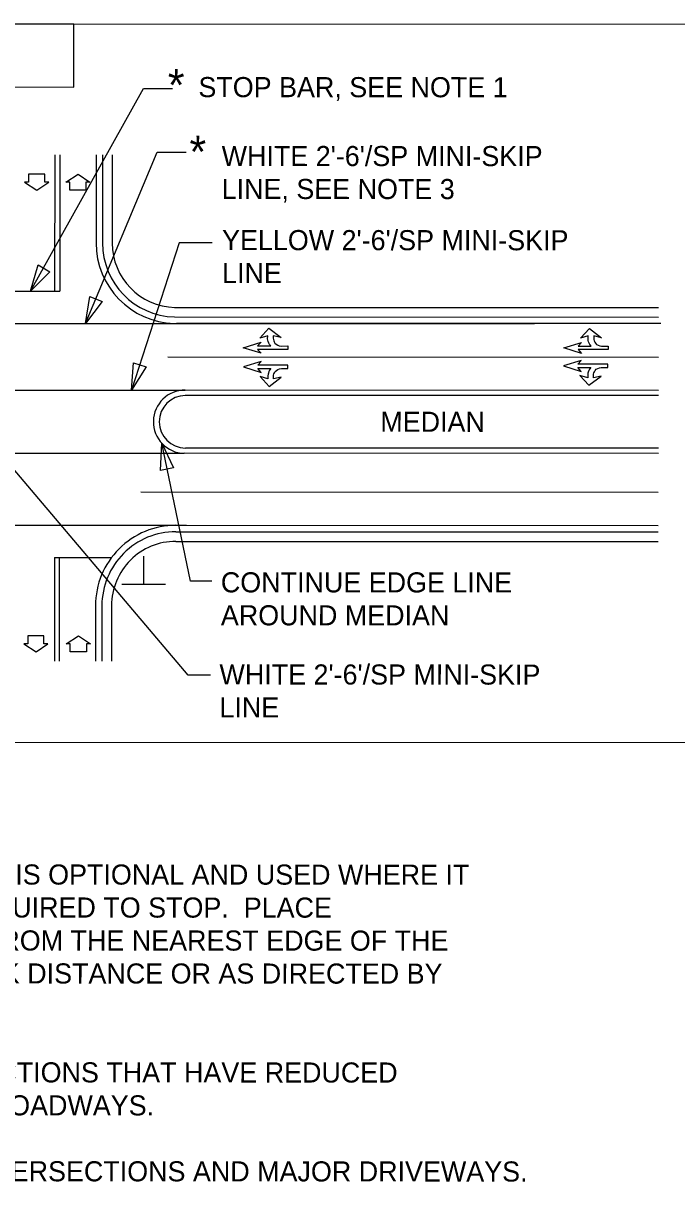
# Model space of a CAD drawing. Extents: x 50667 to 52386, y 46650 to 50479.
# Drawn here: x 51802.6 to 52036.3, y 47079.1 to 47493.3 of the extents above; entities that cross this region are included whole.
import ezdxf

# ---------------------------------------------------------------- set-up
doc = ezdxf.new("R2010")
doc.units = 0
for name, color, linetype in [('Default', 7, 'Continuous'), ('DEV TUBULAR MARKER SECTIONAL VIEW CELL', 7, 'Continuous'), ('Exist Guardrail Text', 7, 'Continuous'), ('Exist Hydro Spring Leader', 7, 'Continuous'), ('Exist Hydro Spring Text', 7, 'Continuous'), ('Exist Utilities Telephone Pole Text Tag Number', 7, 'Continuous'), ('Gray Area Fill Shapes', 7, 'Continuous'), ('Matchline', 7, 'Continuous'), ('Old_Level_49', 7, 'Continuous'), ('Prop EOT Dash', 7, 'Continuous')]:
    doc.layers.add(name, color=color, linetype=linetype)

msp = doc.modelspace()

# ---------------------------------------------------------------- linework, layer by layer
at = {"layer": 'Default'}
for p, q in [((52075.53, 47492.74), (50973.75, 47493.26)), ((51805.21, 47397.44), (51845.59, 47469.94)), ((51845.59, 47469.94), (51855.97, 47469.94)), ((51824.88, 47385.94), (51850.49, 47447.19)), ((51850.49, 47447.19), (51860.87, 47447.19)), ((51813.87, 47446.16), (51813.85, 47397.44)), ((51815.71, 47446.16), (51815.69, 47397.44)), ((51858.35, 47414.74), (51841.34, 47362.08)), ((51870.2, 47414.73), (51858.35, 47414.74)), ((51795.28, 47397.45), (51815.69, 47397.44)), ((51825.58, 47387.99), (51824.88, 47385.94)), ((52030.54, 47385.84), (51857.37, 47385.92)), ((52029.68, 47362), (51860.56, 47362.08)), ((52029.68, 47360.1), (51860.56, 47360.18)), ((51861.63, 47260.23), (51794.41, 47339.52)), ((51862.36, 47293.74), (51852.12, 47343.14)), ((52029.67, 47339.41), (51860.19, 47339.49)), ((52029.67, 47341.29), (51860.57, 47341.37)), ((51813.78, 47302.29), (51813.76, 47265.22)), ((51813.78, 47302.29), (51834.19, 47302.28)), ((51815.5, 47302.29), (51815.48, 47265.22)), ((51870.04, 47293.73), (51862.36, 47293.74)), ((51828.43, 47285.03), (51828.42, 47265.22)), ((51830.73, 47285.03), (51830.72, 47265.21)), ((51834.18, 47285.03), (51834.17, 47265.21)), ((51869.61, 47260.23), (51861.63, 47260.23)), ((52075.41, 47236.01), (50973.63, 47236.53))]:
    msp.add_line(p, q, dxfattribs=at)
for centre, radius, start, end in [((51857.4, 47414.66), 28.75, 179.9734, 268.494), ((51857.4, 47414.66), 26.45, 179.9734, 268.494), ((51857.4, 47414.66), 23, 179.9734, 268.494), ((51860.45, 47350.78), 11.3, 89.479, 268.6341), ((51860.64, 47350.77), 9.4, 90.4385, 269.5936), ((51857.19, 47285.01), 28.75, 89.9734, 179.9734), ((51857.19, 47285.01), 26.45, 89.9734, 179.9734), ((51857.19, 47285.01), 23, 89.9734, 179.9734)]:
    msp.add_arc(centre, radius, start, end, dxfattribs=at)
at = {"layer": 'DEV TUBULAR MARKER SECTIONAL VIEW CELL'}
msp.add_lwpolyline([(51462.35, 47470.51), (51820.66, 47470.34), (51820.67, 47492.86), (51462.36, 47493.03)], close=True, dxfattribs=at)
at = {"layer": 'Exist Guardrail Text'}
for p, q in [((51845.73, 47292.65), (51845.74, 47302.71)), ((51837.91, 47292.65), (51853.43, 47292.65))]:
    msp.add_line(p, q, dxfattribs=at)
at = {"layer": 'Exist Hydro Spring Leader'}
msp.add_line((51770.73, 47362.1), (51860.55, 47362.06), dxfattribs=at)
at = {"layer": 'Exist Hydro Spring Text'}
for p, q in [((51773.03, 47385.96), (51856.64, 47385.92)), ((51774.15, 47339.53), (51859.91, 47339.49)), ((51772.11, 47313.8), (51861.02, 47313.76))]:
    msp.add_line(p, q, dxfattribs=at)
at = {"layer": 'Exist Utilities Telephone Pole Text Tag Number'}
for p, q in [((51854.28, 47373.96), (52029.68, 47373.88)), ((51844.71, 47325.66), (52029.66, 47325.58))]:
    msp.add_line(p, q, dxfattribs=at)
at = {"layer": 'Gray Area Fill Shapes'}
for p, q in [((51828.65, 47446.15), (51828.64, 47413.95)), ((51830.95, 47446.15), (51830.94, 47413.95)), ((51834.4, 47446.15), (51834.39, 47413.95))]:
    msp.add_line(p, q, dxfattribs=at)
for points in [[(51804.54, 47439.32), (51804.54, 47436.44), (51803.1, 47436.44), (51807.46, 47433.57), (51811.72, 47436.44), (51810.29, 47436.44), (51810.29, 47439.32)], [(51819.28, 47433.53), (51819.28, 47436.4), (51817.85, 47436.4), (51822.21, 47439.28), (51826.47, 47436.4), (51825.03, 47436.4), (51825.03, 47433.52)], [(51804.27, 47274.29), (51804.27, 47271.41), (51802.83, 47271.41), (51807.19, 47268.54), (51811.45, 47271.41), (51810.02, 47271.41), (51810.02, 47274.29)], [(51819.44, 47268.5), (51819.44, 47271.37), (51818, 47271.37), (51822.37, 47274.25), (51826.63, 47271.37), (51825.19, 47271.37), (51825.19, 47268.49)]]:
    msp.add_lwpolyline(points, close=True, dxfattribs=at)
at = {"layer": 'Matchline'}
for points in [[(51897.18, 47376.6), (51886.38, 47376.61), (51887.63, 47375.26), (51881.3, 47377.23), (51887.63, 47379.2), (51886.38, 47377.85), (51891.08, 47377.85), (51890.63, 47378.42), (51890.37, 47378.86), (51890.17, 47379.42), (51890.07, 47379.88), (51889.99, 47380.46), (51890.02, 47381.48), (51887.22, 47380.66), (51890.44, 47384.18), (51894.8, 47380.86), (51891.99, 47381.48), (51892.01, 47380.68), (51892.03, 47380.2), (51892.15, 47379.72), (51892.37, 47379.3), (51892.61, 47378.88), (51893.04, 47378.46), (51893.58, 47378.14), (51894.16, 47377.94), (51894.82, 47377.84), (51897.18, 47377.85)], [(51897.18, 47376.6), (51886.38, 47376.61), (51887.63, 47375.26), (51881.3, 47377.23), (51887.63, 47379.2), (51886.38, 47377.85), (51891.08, 47377.85), (51890.63, 47378.42), (51890.37, 47378.86), (51890.17, 47379.42), (51890.07, 47379.88), (51889.99, 47380.46), (51890.02, 47381.48), (51887.22, 47380.66), (51890.44, 47384.18), (51894.8, 47380.86), (51891.99, 47381.48), (51892.01, 47380.68), (51892.03, 47380.2), (51892.15, 47379.72), (51892.37, 47379.3), (51892.61, 47378.88), (51893.04, 47378.46), (51893.58, 47378.14), (51894.16, 47377.94), (51894.82, 47377.84), (51897.18, 47377.85)], [(52011.75, 47376.55), (52000.95, 47376.55), (52002.2, 47375.2), (51995.87, 47377.18), (52002.2, 47379.15), (52000.96, 47377.8), (52005.65, 47377.8), (52005.2, 47378.37), (52004.94, 47378.81), (52004.74, 47379.37), (52004.64, 47379.82), (52004.56, 47380.4), (52004.59, 47381.43), (52001.79, 47380.6), (52005.01, 47384.13), (52009.37, 47380.81), (52006.56, 47381.43), (52006.58, 47380.62), (52006.6, 47380.14), (52006.72, 47379.66), (52006.94, 47379.25), (52007.18, 47378.83), (52007.61, 47378.41), (52008.15, 47378.09), (52008.73, 47377.89), (52009.39, 47377.79), (52011.75, 47377.79)], [(52011.75, 47376.55), (52000.95, 47376.55), (52002.2, 47375.2), (51995.87, 47377.18), (52002.2, 47379.15), (52000.96, 47377.8), (52005.65, 47377.8), (52005.2, 47378.37), (52004.94, 47378.81), (52004.74, 47379.37), (52004.64, 47379.82), (52004.56, 47380.4), (52004.59, 47381.43), (52001.79, 47380.6), (52005.01, 47384.13), (52009.37, 47380.81), (52006.56, 47381.43), (52006.58, 47380.62), (52006.6, 47380.14), (52006.72, 47379.66), (52006.94, 47379.25), (52007.18, 47378.83), (52007.61, 47378.41), (52008.15, 47378.09), (52008.73, 47377.89), (52009.39, 47377.79), (52011.75, 47377.79)], [(51897.25, 47371), (51886.45, 47371.01), (51887.7, 47372.36), (51881.36, 47370.39), (51887.7, 47368.41), (51886.45, 47369.76), (51891.15, 47369.76), (51890.69, 47369.19), (51890.43, 47368.75), (51890.24, 47368.19), (51890.14, 47367.73), (51890.06, 47367.15), (51890.08, 47366.13), (51887.28, 47366.96), (51890.5, 47363.43), (51894.86, 47366.75), (51892.05, 47366.13), (51892.07, 47366.93), (51892.09, 47367.41), (51892.21, 47367.89), (51892.43, 47368.31), (51892.67, 47368.73), (51893.11, 47369.15), (51893.65, 47369.47), (51894.23, 47369.67), (51894.89, 47369.77), (51897.25, 47369.76)], [(51897.25, 47371), (51886.45, 47371.01), (51887.7, 47372.36), (51881.36, 47370.39), (51887.7, 47368.41), (51886.45, 47369.76), (51891.15, 47369.76), (51890.69, 47369.19), (51890.43, 47368.75), (51890.24, 47368.19), (51890.14, 47367.73), (51890.06, 47367.15), (51890.08, 47366.13), (51887.28, 47366.96), (51890.5, 47363.43), (51894.86, 47366.75), (51892.05, 47366.13), (51892.07, 47366.93), (51892.09, 47367.41), (51892.21, 47367.89), (51892.43, 47368.31), (51892.67, 47368.73), (51893.11, 47369.15), (51893.65, 47369.47), (51894.23, 47369.67), (51894.89, 47369.77), (51897.25, 47369.76)], [(52011.63, 47371.36), (52000.83, 47371.37), (52002.08, 47372.71), (51995.74, 47370.75), (52002.07, 47368.77), (52000.83, 47370.12), (52005.53, 47370.12), (52005.07, 47369.55), (52004.81, 47369.11), (52004.61, 47368.55), (52004.51, 47368.09), (52004.43, 47367.51), (52004.46, 47366.48), (52001.66, 47367.32), (52004.87, 47363.79), (52009.24, 47367.1), (52006.43, 47366.48), (52006.45, 47367.29), (52006.47, 47367.77), (52006.59, 47368.25), (52006.81, 47368.67), (52007.05, 47369.09), (52007.49, 47369.51), (52008.03, 47369.83), (52008.6, 47370.02), (52009.26, 47370.12), (52011.63, 47370.11)], [(52011.63, 47371.36), (52000.83, 47371.37), (52002.08, 47372.71), (51995.74, 47370.75), (52002.07, 47368.77), (52000.83, 47370.12), (52005.53, 47370.12), (52005.07, 47369.55), (52004.81, 47369.11), (52004.61, 47368.55), (52004.51, 47368.09), (52004.43, 47367.51), (52004.46, 47366.48), (52001.66, 47367.32), (52004.87, 47363.79), (52009.24, 47367.1), (52006.43, 47366.48), (52006.45, 47367.29), (52006.47, 47367.77), (52006.59, 47368.25), (52006.81, 47368.67), (52007.05, 47369.09), (52007.49, 47369.51), (52008.03, 47369.83), (52008.6, 47370.02), (52009.26, 47370.12), (52011.63, 47370.11)]]:
    msp.add_lwpolyline(points, close=True, dxfattribs=at)
at = {"layer": 'Old_Level_49'}
for p, q in [((51856.64, 47391.67), (52029.69, 47391.59)), ((51856.64, 47388.22), (52029.69, 47388.14)), ((51856.64, 47385.92), (51985.39, 47385.86)), ((51857.2, 47313.76), (52029.65, 47313.68)), ((51857.2, 47311.46), (52029.65, 47311.38)), ((51857.2, 47308.01), (52029.65, 47307.93))]:
    msp.add_line(p, q, dxfattribs=at)
at = {"layer": 'Prop EOT Dash'}
for points in [[(51812.07, 47404.41), (51805.21, 47397.44), (51807.98, 47406.82)], [(51812.07, 47404.41), (51805.21, 47397.44), (51807.98, 47406.82)], [(51830.79, 47393.73), (51824.88, 47385.94), (51826.42, 47395.59)], [(51830.79, 47393.73), (51824.88, 47385.94), (51826.42, 47395.59)], [(51846.51, 47370.38), (51841.34, 47362.08), (51842, 47371.84)], [(51846.51, 47370.38), (51841.34, 47362.08), (51842, 47371.84)], [(51851.73, 47333.37), (51852.12, 47343.14), (51856.37, 47334.33)], [(51851.73, 47333.37), (51852.12, 47343.14), (51856.37, 47334.33)]]:
    msp.add_lwpolyline(points, close=True, dxfattribs=at)

# ---------------------------------------------------------------- texts
at = {"layer": 'Default'}
for s, height, p in [('*', 11.5, (51854.31, 47465.4)), ('STOP BAR, SEE NOTE 1', 7.1874, (51865.24, 47466.81)), ('*', 11.5, (51862.04, 47441.54)), ("WHITE 2'-6'/SP MINI-SKIP", 7.1874, (51873.55, 47442.19)), ('LINE, SEE NOTE 3', 7.1874, (51873.55, 47430.4)), ("YELLOW 2'-6'/SP MINI-SKIP", 7.1874, (51873.7, 47412.12)), ('LINE', 7.187, (51873.7, 47400.33)), ('MEDIAN', 7.187, (51930.27, 47347.18)), ('CONTINUE EDGE LINE', 7.1874, (51873.27, 47289.78)), ('AROUND MEDIAN ', 7.1874, (51873.27, 47277.99)), ("WHITE 2'-6'/SP MINI-SKIP", 7.1874, (51872.76, 47256.85)), ('LINE', 7.187, (51872.76, 47245.07)), ('1- PLACEMENT OF STOP BARS AT NON-SIGNALIZED INTERSECTIONS IS OPTIONAL AND USED WHERE IT', 7.1874, (51473.48, 47185.48)), ('   IS IMPORTANT TO INDICATE THE POINT WHICH VEHICLES ARE REQUIRED TO STOP.  PLACE ', 7.1874, (51473.47, 47173.69)), ('   STOP BARS NO LESS THAN 4 FEET AND NO MORE THAN 30 FEET FROM THE NEAREST EDGE OF THE', 7.1874, (51473.47, 47161.9)), ('   INTERSECTING ROADWAY.  USE 10 FEET AS THE TYPICAL SETBACK DISTANCE OR AS DIRECTED BY', 7.1874, (51473.46, 47150.11)), ('2- MINI-SKIP LANE LINE EXTENSIONS SHOULD BE USED AT INTERSECTIONS THAT HAVE REDUCED', 7.1874, (51473.44, 47114.75)), ('   VISIBILITY CONDITIONS SUCH AS OFFSET, SKEWED, OR CURVED ROADWAYS.', 7.1874, (51473.44, 47102.96)), ('3- MINI-SKIP EDGE LINE EXTENSIONS MAY BE PLACED THROUGH INTERSECTIONS AND MAJOR DRIVEWAYS.', 7.1874, (51473.43, 47079.39))]:
    msp.add_text(s, height=height, rotation=359.9734, dxfattribs=at).set_placement(p)

doc.saveas('drawing.dxf')
